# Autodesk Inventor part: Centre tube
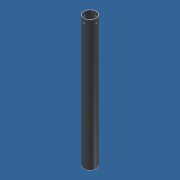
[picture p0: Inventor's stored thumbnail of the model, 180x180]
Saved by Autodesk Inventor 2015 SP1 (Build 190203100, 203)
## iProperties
Category: Mechanical Engineering Drawing and Design - CADD
Manager: Fábio Ricardo de Oliveira Souza
Company: SENAI - Serviço Nacional de Aprendizagem Industrial
Created: 2011-06
Part Number: Centre tube
Material: Steel
Description: Stainless Steel (DIN- X6CrNiTi18-10)
Document SubType Name: Modeling
Designer: Guilherme Augusto Franco de Souza
Engineer: George Geraldo de Oliveia Silva
Authority: Fábio Ricardo de Oliveira Soza
Density: 7.85 g/cm^3
Appearance: Machined 02
Subject: WorldSkill 2011 - London, England
Author: Guilherme Augusto Franco de Souza
Revision Number: 00
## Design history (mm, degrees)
sketch "Sketch2"
  geometry: C1 r 38.05 at (0, 0); 1 further point
  constraints: 1 centre point, 1 coincident
  dimensions: "d2" = 76.1 diameter of C1
extrude "Extrusion2" new body sketch "Sketch2" stored distance "d3" = 800; taper "d4" = 0 deg
shell "Shell1" dims "d5" = 1.6
sketch "Sketch3"
  geometry: L1 (-38.05, 400)-(38.05, 400) reference; C1 r 3.5 at (0, 375); 1 further point
  constraints: 1 centre point, 1 vertical alignment
  dimensions: "d7" = 7 diameter of C1; "d8" = 25 distance from line of L1 C1.centre
hole "Hole1" sketch "Sketch3" at (0, 375) diameter "d14" = 4.917; stored, may be unused: countersink angle "d18" = 90 deg, drill point angle "d20" = 118 deg; dims "d15" = 6, "d16" = 4, "d17" = 2, "d19" = 8
pattern_circular "Circular Pattern1" dims angle "d12" = 360 deg
body "Solid2"
